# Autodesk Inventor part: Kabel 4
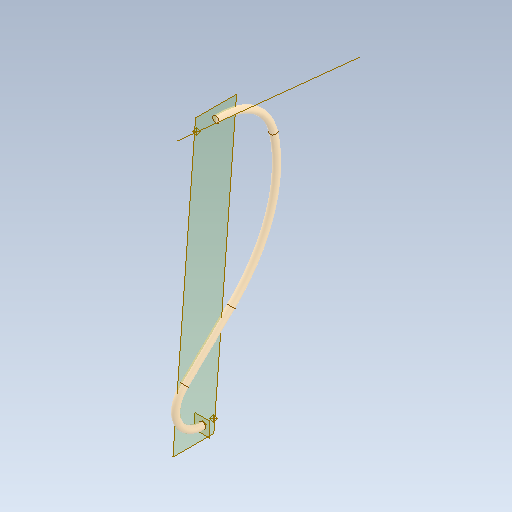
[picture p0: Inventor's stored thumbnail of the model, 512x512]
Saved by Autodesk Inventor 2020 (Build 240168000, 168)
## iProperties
Created: 2025-04
Part Number: Kabel 4
Material: Polyetylen, S vysokou hustotou
Document SubType Name: Modeling
Designer: doma
Density: 0.952 g/cm^3
Appearance: Hladká – špinavě bílá
Author: doma
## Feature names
1. Tažení1
## Parameters: d1 = 5 mm, d2 = 0, d3 = 0
